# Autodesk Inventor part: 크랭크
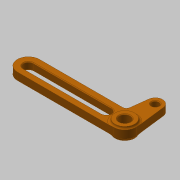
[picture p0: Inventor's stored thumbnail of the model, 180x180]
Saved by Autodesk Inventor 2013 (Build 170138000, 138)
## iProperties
Created: 2019-09
Part Number: 크랭크
Material: 알루미늄 6061
Document SubType Name: Modeling
Designer: mduedu
Density: 2.71 g/cm^3
Mass: 23.0161 g
Surface Area: 54.7149 cm^2
Volume: 8.49301 cm^3
Author: mduedu
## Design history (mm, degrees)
sketch "스케치1"
  geometry: L1 (0, 0)-(79, 0); L2 (0, 9)-(79, 9); L3 (10.637, -9)-(79, -9); L4 (0, 0)-(0, -25); L5 (-8.935, -1.08)-(-5.957, -25.72); L6 (7.659, -11.64)-(5.957, -25.72); L7 (79, -4)-(15, -4); L8 (15, 4)-(79, 4); C1 r 3 at (0, -25); A1 r 9 centre (0, 0) between (0, 9) and (-8.935, -1.08); A2 r 9 centre (79, 0) between (79, -9) and (79, 9); A3 r 6 centre (0, -25) between (-5.957, -25.72) and (5.957, -25.72); A4 r 3 centre (10.637, -12) between (10.637, -9) and (7.659, -11.64); A5 r 4 centre (79, 0) between (79, -4) and (79, 4); A6 r 4 centre (15, 0) between (15, -4) and (15, 4); 1 further point
  constraints: 16 end point, 13 point on circle, 12 tangent, 7 centre point, 5 coincident, 3 horizontal, 2 point on line, 1 equal radius, 1 perpendicular, 1 other
  dimensions: "d0" = 79 distance of L1.start L1.end; "d2" = 25 distance of L1.start L4.end; "d3" = 3 radius of A4; "d4" = 9 radius of A1; "d5" = 6 radius of A3; "d6" = 8 diameter of A5; "d7" = 64 distance of A6.centre L1.end; "d8" = 6 diameter of C1
extrude "돌출1" new body sketch "스케치1" stored distance "d9" = 6; taper "d10" = 0 deg
sketch "스케치2"
  geometry: C1 r 8 at (0, 0); 1 further point
  constraints: 1 centre point, 1 coincident
  dimensions: "d11" = 16 diameter of C1
extrude "돌출2" join sketch "스케치2" stored distance "d12" = 10; taper "d13" = 0 deg
sketch "스케치3"
  geometry: C1 r 4.5 at (0, 0); 1 further point
  constraints: 1 centre point, 1 coincident
  dimensions: "d14" = 9 diameter of C1
extrude "돌출3" cut sketch "스케치3" stored distance "d15" = 10; taper "d16" = 0 deg
fillet "모깎기1" dims "d17" = 2
chamfer "모따기1" distance "d18" = 0.5; stored, may be unused: second distance "d19" = 2, angle "d20" = 45 deg
node "솔리드1"
